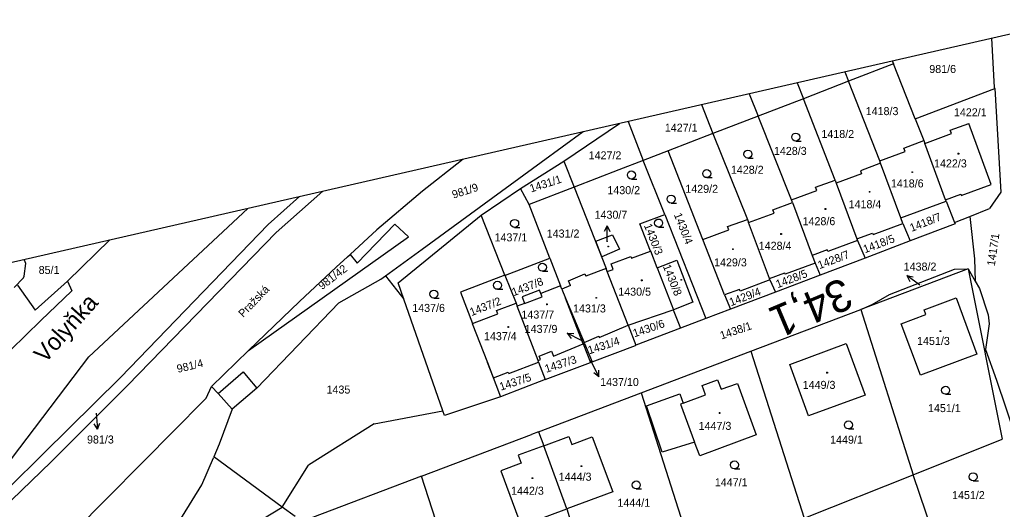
# Model space of a CAD drawing. Extents: x -805730 to -804640, y -1150889 to -1150366.
# Drawn here: x -805108.7 to -804924.5, y -1150504.4 to -1150412.8 of the extents above; entities that cross this region are included whole.
import ezdxf

# ---------------------------------------------------------------- set-up
doc = ezdxf.new("R2010")
doc.units = 0
for name, color, linetype in [('Default', 7, 'Continuous'), ('formát', 7, 'Continuous'), ('kilometráž - vrstava 7', 7, 'Continuous'), ('kn_celek - Cisla parcel pomocna', 7, 'Continuous'), ('kn_celek - Cisla pozemkovych parcel', 7, 'Continuous'), ('kn_celek - Cisla stavebnich parcel', 7, 'Continuous'), ('kn_celek - Dalsi prvky mapy popis', 7, 'Continuous'), ('kn_celek - Hranice parcel', 7, 'Continuous'), ('kn_celek - Vnitrni kresby', 7, 'Continuous'), ('kn_celek - Znacky budov', 7, 'Continuous'), ('kn_celek - Znacky kultur', 7, 'Continuous')]:
    doc.layers.add(name, color=color, linetype=linetype)

# ---------------------------------------------------------------- blocks, each defined once
blk = doc.blocks.new('304')
at = {"layer": 'Default'}
blk.add_line((-0.1, 0), (9.9, 0), dxfattribs=at)
blk.add_circle((-0.1, 7.5), 7.5, dxfattribs=at)
blk = doc.blocks.new('402')
at = {"layer": 'Default'}
for p, q in [((-0.8, 0.8), (0.7, 0.8)), ((-0.8, 0.8), (-0.8, -0.7)), ((0.7, 0.8), (0.7, -0.7)), ((0.7, -0.7), (-0.8, -0.7))]:
    blk.add_line(p, q, dxfattribs=at)
blk = doc.blocks.new('Z61')
at = {"layer": 'Default'}
for p, q in [((0, 0), (30, 0)), ((30, 0), (19.2, 5.3)), ((30, 0), (19.2, -5.3))]:
    blk.add_line(p, q, dxfattribs=at)

msp = doc.modelspace()

# ---------------------------------------------------------------- linework, layer by layer
at = {"layer": 'formát'}
msp.add_line((-804911.33, -1150412.76), (-805116.05, -1150459.54), dxfattribs=at)
at = {"layer": 'kn_celek - Cisla parcel pomocna'}
for p, q in [((-805002.99, -1150473.03), (-805003.39, -1150472.83)), ((-805001.75, -1150476.54), (-805001.53, -1150476.96))]:
    msp.add_line(p, q, dxfattribs=at)
at = {"layer": 'kn_celek - Hranice parcel'}
for p, q in [((-804925.96, -1150425.46), (-804926.47, -1150416.22)), ((-804945.14, -1150420.48), (-804944.93, -1150421.05)), ((-804944.93, -1150421.05), (-804953.35, -1150424.29)), ((-804940.85, -1150431.33), (-804944.93, -1150421.05)), ((-804954.05, -1150422.52), (-804953.35, -1150424.29)), ((-804962.97, -1150424.56), (-804961.8, -1150427.56)), ((-804953.35, -1150424.29), (-804961.8, -1150427.56)), ((-804947.5, -1150439.18), (-804953.35, -1150424.29)), ((-804940.85, -1150431.33), (-804925.94, -1150425.67)), ((-804925.94, -1150425.67), (-804925.96, -1150425.46)), ((-804925.94, -1150425.67), (-804924.82, -1150445.04)), ((-804971.98, -1150426.62), (-804970.29, -1150430.83)), ((-804961.8, -1150427.56), (-804970.29, -1150430.83)), ((-804955.86, -1150442.78), (-804961.8, -1150427.56)), ((-804980.9, -1150428.66), (-804978.77, -1150434.1)), ((-804970.29, -1150430.83), (-804978.77, -1150434.1)), ((-804964.03, -1150446.5), (-804970.29, -1150430.83)), ((-804940.85, -1150431.33), (-804939.24, -1150435.41)), ((-805006.72, -1150439.25), (-804996.26, -1150432.17)), ((-804994.64, -1150431.8), (-804991.84, -1150439.15)), ((-804934.3, -1150433.46), (-804930.82, -1150432.17)), ((-804934.07, -1150434.1), (-804934.3, -1150433.46)), ((-804926.59, -1150443.6), (-804930.82, -1150432.17)), ((-805010.94, -1150439.46), (-805003.06, -1150433.72)), ((-804978.77, -1150434.1), (-804987.17, -1150437.34)), ((-804978.77, -1150434.1), (-804972.3, -1150450.15)), ((-804939.04, -1150435.94), (-804934.07, -1150434.1)), ((-804942.95, -1150436.79), (-804939.24, -1150435.41)), ((-804942.73, -1150437.41), (-804942.95, -1150436.79)), ((-804939.24, -1150435.41), (-804939.04, -1150435.94)), ((-804935.14, -1150446.5), (-804939.04, -1150435.94)), ((-805025.57, -1150438.87), (-805025.92, -1150439.12)), ((-804987.17, -1150437.34), (-804991.84, -1150439.15)), ((-804980.64, -1150453.92), (-804987.17, -1150437.34)), ((-804947.5, -1150439.18), (-804942.73, -1150437.41)), ((-805033.29, -1150455.72), (-805010.94, -1150439.46)), ((-805025.92, -1150439.12), (-805033.21, -1150444.86)), ((-805014.86, -1150444.38), (-805006.72, -1150439.25)), ((-805006.72, -1150439.25), (-805004.8, -1150444.14)), ((-804991.84, -1150439.15), (-804996.39, -1150440.9)), ((-804987.78, -1150449.21), (-804991.84, -1150439.15)), ((-804947.35, -1150439.63), (-804951.12, -1150441.03)), ((-804947.35, -1150439.63), (-804947.5, -1150439.18)), ((-804943.54, -1150449.86), (-804947.35, -1150439.63)), ((-804996.39, -1150440.9), (-805004.8, -1150444.14)), ((-804950.91, -1150441.62), (-804955.64, -1150443.37)), ((-804951.12, -1150441.03), (-804950.91, -1150441.62)), ((-805022.22, -1150449.34), (-805014.86, -1150444.38)), ((-805013.21, -1150447.39), (-805014.86, -1150444.38)), ((-805004.8, -1150444.14), (-805013.21, -1150447.39)), ((-805004.8, -1150444.14), (-804998.8, -1150459.32)), ((-804959.52, -1150444.15), (-804955.86, -1150442.78)), ((-804959.3, -1150444.74), (-804959.52, -1150444.15)), ((-804955.86, -1150442.78), (-804955.64, -1150443.37)), ((-804955.64, -1150443.37), (-804951.76, -1150453.81)), ((-804932.21, -1150445.68), (-804926.59, -1150443.6)), ((-805062.11, -1150451.14), (-805056.24, -1150445.88)), ((-805060.64, -1150452.61), (-805051.86, -1150444.87)), ((-805033.21, -1150444.86), (-805041.78, -1150452.12)), ((-804964.03, -1150446.5), (-804959.3, -1150444.74)), ((-804935.14, -1150446.5), (-804932.3, -1150445.45)), ((-804932.3, -1150445.45), (-804932.21, -1150445.68)), ((-804924.82, -1150445.04), (-804926.9, -1150448.13)), ((-805065.94, -1150448.09), (-805095.74, -1150475.92)), ((-805009.33, -1150457.41), (-805013.21, -1150447.39)), ((-804967.51, -1150448.35), (-804963.85, -1150446.99)), ((-804963.85, -1150446.99), (-804964.03, -1150446.5)), ((-804963.85, -1150446.99), (-804960.15, -1150456.93)), ((-804943.54, -1150449.86), (-804935.05, -1150446.74)), ((-804935.05, -1150446.74), (-804935.14, -1150446.5)), ((-804935.05, -1150446.74), (-804933.47, -1150450.72)), ((-804930.64, -1150449.61), (-804926.9, -1150448.13)), ((-805037.75, -1150462.05), (-805022.22, -1150449.34)), ((-805017.74, -1150460.61), (-805022.22, -1150449.34)), ((-804992.45, -1150450.99), (-804987.78, -1150449.21)), ((-804987.78, -1150449.21), (-804980.08, -1150468.73)), ((-804972.08, -1150450.74), (-804967.29, -1150448.96)), ((-804967.29, -1150448.96), (-804967.51, -1150448.35)), ((-804943.15, -1150450.92), (-804943.54, -1150449.86)), ((-804933.47, -1150450.72), (-804930.64, -1150449.61)), ((-804930.64, -1150449.61), (-804929.74, -1150457.55)), ((-805089.82, -1150479.75), (-805062.11, -1150451.14)), ((-805045.42, -1150458.33), (-805038.38, -1150451.03)), ((-805038.38, -1150451.03), (-805035.81, -1150453.4)), ((-804990.46, -1150456.1), (-804992.45, -1150450.99)), ((-804976.01, -1150451.51), (-804972.3, -1150450.15)), ((-804975.79, -1150452.11), (-804976.01, -1150451.51)), ((-804972.3, -1150450.15), (-804972.08, -1150450.74)), ((-804968.18, -1150461.2), (-804972.08, -1150450.74)), ((-804948.75, -1150453.01), (-804943.15, -1150450.92)), ((-804943.15, -1150450.92), (-804941.8, -1150454.19)), ((-804933.37, -1150450.99), (-804941.8, -1150454.19)), ((-804933.47, -1150450.72), (-804933.37, -1150450.99)), ((-805088.49, -1150481.25), (-805060.64, -1150452.61)), ((-805065.83, -1150474.73), (-805035.81, -1150453.4)), ((-805046.78, -1150456.73), (-805041.78, -1150452.12)), ((-805000.72, -1150454.24), (-804997.56, -1150453.02)), ((-804997.56, -1150453.02), (-804996.29, -1150455.7)), ((-804980.64, -1150453.92), (-804975.79, -1150452.11)), ((-804951.76, -1150453.81), (-804948.86, -1150452.73)), ((-804948.86, -1150452.73), (-804948.75, -1150453.01)), ((-805091.78, -1150454), (-805099.75, -1150461.7)), ((-804999.59, -1150457.14), (-805000.72, -1150454.24)), ((-804976.62, -1150464.31), (-804980.64, -1150453.92)), ((-804951.66, -1150454.09), (-804957.23, -1150456.16)), ((-804951.76, -1150453.81), (-804951.66, -1150454.09)), ((-804951.66, -1150454.09), (-804950.22, -1150457.39)), ((-804941.8, -1150454.19), (-804950.22, -1150457.39)), ((-805049.37, -1150459.12), (-805047.26, -1150457.17)), ((-805047.26, -1150457.17), (-805046.78, -1150456.73)), ((-805046.78, -1150456.73), (-805045.42, -1150458.33)), ((-805040.15, -1150460.71), (-805033.29, -1150455.72)), ((-805017.67, -1150460.58), (-805009.33, -1150457.41)), ((-805009.33, -1150457.41), (-805007.32, -1150462.6)), ((-804996.29, -1150455.7), (-804999.59, -1150457.14)), ((-804997.85, -1150458.47), (-804994.15, -1150457.13)), ((-804994.15, -1150457.13), (-804994.05, -1150457.41)), ((-804994.05, -1150457.41), (-804990.46, -1150456.1)), ((-804990.46, -1150456.1), (-804990.43, -1150456.09)), ((-804989.2, -1150459.22), (-804990.43, -1150456.09)), ((-804957.33, -1150455.88), (-804960.15, -1150456.93)), ((-804960.15, -1150456.93), (-804959.58, -1150458.33)), ((-804950.22, -1150457.39), (-804958.64, -1150460.58)), ((-804957.23, -1150456.16), (-804957.33, -1150455.88)), ((-805107.65, -1150458.1), (-805107.89, -1150457.68)), ((-805107.85, -1150460.8), (-805107.58, -1150458.42)), ((-805107.58, -1150458.42), (-805107.65, -1150458.1)), ((-805056.28, -1150465.5), (-805049.37, -1150459.12)), ((-804997.47, -1150459.51), (-804997.85, -1150458.47)), ((-804989.2, -1150459.22), (-804985.56, -1150457.81)), ((-804989.2, -1150459.22), (-804986.16, -1150467.06)), ((-804985.56, -1150457.81), (-804982.53, -1150465.66)), ((-804959.58, -1150458.33), (-804965.21, -1150460.41)), ((-804959.58, -1150458.33), (-804958.64, -1150460.58)), ((-804929.74, -1150457.55), (-804929.58, -1150461.7)), ((-805108.02, -1150461.11), (-805107.85, -1150460.8)), ((-805040.99, -1150461.32), (-805040.15, -1150460.71)), ((-805040.15, -1150460.71), (-805036.69, -1150465.09)), ((-805017.74, -1150460.61), (-805026.06, -1150463.77)), ((-805017.67, -1150460.58), (-805017.74, -1150460.61)), ((-805017.74, -1150460.61), (-805015.66, -1150465.83)), ((-805005.86, -1150461.65), (-805002.76, -1150460.36)), ((-805002.76, -1150460.36), (-805002.59, -1150460.77)), ((-804998.8, -1150459.32), (-805002.59, -1150460.77)), ((-804998.57, -1150459.91), (-804998.8, -1150459.32)), ((-804998.57, -1150459.91), (-804997.47, -1150459.51)), ((-804994.64, -1150469.99), (-804998.57, -1150459.91)), ((-804968.18, -1150461.2), (-804965.31, -1150460.13)), ((-804958.64, -1150460.58), (-804967.06, -1150463.78)), ((-804965.21, -1150460.41), (-804965.31, -1150460.13)), ((-804930.92, -1150459.44), (-804951.04, -1150467.05)), ((-804945.64, -1150464.19), (-804933.47, -1150459.45)), ((-804933.47, -1150459.45), (-804930.92, -1150459.44)), ((-804930.92, -1150459.44), (-804924.52, -1150491.32)), ((-804930.92, -1150459.44), (-804929.58, -1150461.7)), ((-805109.72, -1150462.89), (-805108.02, -1150461.11)), ((-805109.13, -1150462.48), (-805105.81, -1150467.16)), ((-805105.81, -1150467.16), (-805099.75, -1150461.7)), ((-805099.75, -1150461.7), (-805098.94, -1150463.51)), ((-805048.88, -1150465.79), (-805040.99, -1150461.32)), ((-805036.69, -1150465.09), (-805037.75, -1150462.05)), ((-805007.32, -1150462.6), (-805011.02, -1150464.02)), ((-805007.08, -1150463.23), (-805007.32, -1150462.6)), ((-805005.48, -1150462.56), (-805007.08, -1150463.23)), ((-805005.48, -1150462.56), (-805005.86, -1150461.65)), ((-804968.08, -1150461.49), (-804973.66, -1150463.57)), ((-804968.08, -1150461.49), (-804968.18, -1150461.2)), ((-804968.08, -1150461.49), (-804967.06, -1150463.78)), ((-804929.58, -1150461.7), (-804928.77, -1150463.07)), ((-805098.94, -1150463.51), (-805104.72, -1150469.11)), ((-805026.06, -1150463.77), (-805023.82, -1150469.64)), ((-805011.25, -1150463.41), (-805014.55, -1150464.68)), ((-805014.55, -1150464.68), (-805014.08, -1150465.89)), ((-805011.02, -1150464.02), (-805011.25, -1150463.41)), ((-805007.08, -1150463.23), (-805006.39, -1150464.89)), ((-804973.77, -1150463.28), (-804976.62, -1150464.31)), ((-804976.62, -1150464.31), (-804975.47, -1150466.98)), ((-804967.06, -1150463.78), (-804975.47, -1150466.98)), ((-804973.66, -1150463.57), (-804973.77, -1150463.28)), ((-804948.92, -1150466.09), (-804945.64, -1150464.19)), ((-804928.77, -1150463.07), (-804927.15, -1150468.03)), ((-805065.83, -1150474.73), (-805056.28, -1150465.5)), ((-805064.25, -1150481.77), (-805048.88, -1150465.79)), ((-805029.41, -1150485.99), (-805036.69, -1150465.09)), ((-805019.31, -1150467.21), (-805015.66, -1150465.83)), ((-805015.66, -1150465.83), (-805015.45, -1150466.42)), ((-805014.08, -1150465.89), (-805015.45, -1150466.42)), ((-805011.54, -1150476.59), (-805015.45, -1150466.42)), ((-805006.39, -1150464.89), (-805002.93, -1150473.2)), ((-805003.08, -1150473.48), (-805006.39, -1150464.89)), ((-804982.53, -1150465.66), (-804986.16, -1150467.06)), ((-804951.04, -1150467.05), (-804948.92, -1150466.09)), ((-804939.15, -1150467.07), (-804933.18, -1150464.83)), ((-804933.18, -1150464.83), (-804929.31, -1150475.36)), ((-805023.82, -1150469.64), (-805019.07, -1150467.82)), ((-805019.07, -1150467.82), (-805019.31, -1150467.21)), ((-804994.64, -1150469.99), (-804986.2, -1150467.07)), ((-804986.16, -1150467.06), (-804986.2, -1150467.07)), ((-804986.2, -1150467.07), (-804984.86, -1150470.54)), ((-804975.47, -1150466.98), (-804980.08, -1150468.73)), ((-804971.65, -1150474.85), (-804951.04, -1150467.05)), ((-804951.04, -1150467.05), (-804941.26, -1150497.99)), ((-804943.5, -1150469.71), (-804938.88, -1150467.94)), ((-804938.88, -1150467.94), (-804939.15, -1150467.07)), ((-804927.15, -1150468.03), (-804927.01, -1150469.74)), ((-805104.72, -1150469.11), (-805110.36, -1150474.57)), ((-805023.82, -1150469.64), (-805023.89, -1150469.67)), ((-805023.89, -1150469.67), (-805021.05, -1150476.92)), ((-805000.08, -1150472.25), (-804994.64, -1150469.99)), ((-804994.64, -1150469.99), (-804993.19, -1150473.71)), ((-804980.08, -1150468.73), (-804984.86, -1150470.54)), ((-804939.83, -1150479.34), (-804943.5, -1150469.71)), ((-804927.01, -1150469.74), (-804927.7, -1150474.5)), ((-805002.93, -1150473.2), (-805000.16, -1150472.05)), ((-805000.16, -1150472.05), (-805000.08, -1150472.25)), ((-804984.86, -1150470.54), (-804993.19, -1150473.71)), ((-805008.65, -1150475.74), (-805003.08, -1150473.48)), ((-805003.08, -1150473.48), (-805002.85, -1150473.39)), ((-805003.08, -1150473.48), (-805001.74, -1150476.95)), ((-805002.85, -1150473.39), (-805002.93, -1150473.2)), ((-805002.85, -1150473.39), (-805001.43, -1150476.83)), ((-805001.43, -1150476.83), (-804993.3, -1150473.75)), ((-804993.19, -1150473.71), (-804993.3, -1150473.75)), ((-804964.38, -1150477.32), (-804953.81, -1150473.42)), ((-804953.81, -1150473.42), (-804950.26, -1150483.04)), ((-805072.76, -1150481.42), (-805065.83, -1150474.73)), ((-805011.36, -1150475.74), (-805009.03, -1150474.8)), ((-805011.09, -1150476.41), (-805011.36, -1150475.74)), ((-805009.03, -1150474.8), (-805008.65, -1150475.74)), ((-804992.2, -1150482.63), (-804971.65, -1150474.85)), ((-804971.65, -1150474.85), (-804961.69, -1150506.13)), ((-804929.31, -1150475.36), (-804939.83, -1150479.34)), ((-804927.7, -1150474.5), (-804925.63, -1150480.28)), ((-805111.59, -1150496.78), (-805095.74, -1150475.92)), ((-805021.05, -1150476.92), (-805018.6, -1150483.36)), ((-805019.92, -1150479.82), (-805021.05, -1150476.92)), ((-805017.02, -1150479.03), (-805011.43, -1150476.87)), ((-805011.54, -1150476.59), (-805011.09, -1150476.41)), ((-805011.43, -1150476.87), (-805011.54, -1150476.59)), ((-805011.43, -1150476.87), (-805010.19, -1150480.16)), ((-805010.19, -1150480.16), (-805001.74, -1150476.95)), ((-805001.74, -1150476.95), (-805001.43, -1150476.83)), ((-804960.83, -1150486.94), (-804964.38, -1150477.32)), ((-805071.49, -1150482.75), (-805066.84, -1150478.72)), ((-805066.84, -1150478.72), (-805065.96, -1150479.76)), ((-805019.92, -1150479.82), (-805017.13, -1150478.76)), ((-805017.13, -1150478.76), (-805017.02, -1150479.03)), ((-805104.33, -1150494.08), (-805089.82, -1150479.75)), ((-805102.8, -1150495.57), (-805088.49, -1150481.25)), ((-805065.96, -1150479.76), (-805064.25, -1150481.77)), ((-805010.19, -1150480.16), (-805018.6, -1150483.36)), ((-804980.8, -1150481.26), (-804977.89, -1150480.19)), ((-804980.16, -1150483.02), (-804980.8, -1150481.26)), ((-804977.89, -1150480.19), (-804977.24, -1150481.95)), ((-804977.24, -1150481.95), (-804974.15, -1150480.88)), ((-804974.15, -1150480.88), (-804970.66, -1150490.48)), ((-804925.63, -1150480.28), (-804920.17, -1150496.45)), ((-805073.74, -1150483.62), (-805072.76, -1150481.42)), ((-805072.76, -1150481.42), (-805071.49, -1150482.75)), ((-805064.25, -1150481.77), (-805068.87, -1150485.69)), ((-805011.47, -1150489.91), (-804992.2, -1150482.63)), ((-804992.2, -1150482.63), (-804982.1, -1150514.26)), ((-804991.24, -1150485.06), (-804984.99, -1150482.82)), ((-804984.99, -1150482.82), (-804984.32, -1150484.55)), ((-804984.32, -1150484.55), (-804980.16, -1150483.02)), ((-804950.26, -1150483.04), (-804960.83, -1150486.94)), ((-805079.46, -1150489.37), (-805074.53, -1150484.41)), ((-805074.53, -1150484.41), (-805073.74, -1150483.62)), ((-805018.6, -1150483.36), (-805029.11, -1150486.86)), ((-805068.87, -1150485.69), (-805071.3, -1150492.22)), ((-805042.24, -1150488.46), (-805029.41, -1150485.99)), ((-805029.11, -1150486.86), (-805029.41, -1150485.99)), ((-804988.29, -1150493.74), (-804991.24, -1150485.06)), ((-805042.24, -1150488.46), (-805054.55, -1150496.18)), ((-805079.5, -1150489.41), (-805112.27, -1150522.42)), ((-805079.46, -1150489.37), (-805079.5, -1150489.41)), ((-805033.4, -1150498.22), (-805012.78, -1150490.41)), ((-805011.47, -1150489.91), (-805012.78, -1150490.41)), ((-805011.47, -1150489.91), (-805010.49, -1150492.55)), ((-804970.66, -1150490.48), (-804981.23, -1150494.42)), ((-805071.3, -1150492.22), (-805072.32, -1150494.62)), ((-805010.49, -1150492.55), (-805005.78, -1150490.79)), ((-805005.78, -1150490.79), (-805005.2, -1150492.28)), ((-805005.2, -1150492.28), (-805001.38, -1150490.85)), ((-805001.38, -1150490.85), (-804997.51, -1150501.2)), ((-804982.19, -1150491.84), (-804988.29, -1150493.74)), ((-804981.23, -1150494.42), (-804982.19, -1150491.84)), ((-804941.26, -1150497.99), (-804924.52, -1150491.32)), ((-805110.75, -1150500.43), (-805104.33, -1150494.08)), ((-805010.49, -1150492.55), (-805015.26, -1150494.31)), ((-805006.12, -1150504.36), (-805010.49, -1150492.55)), ((-805110.22, -1150502.75), (-805102.8, -1150495.57)), ((-805074.55, -1150499.86), (-805072.39, -1150494.78)), ((-805072.32, -1150494.62), (-805072.39, -1150494.78)), ((-805059.52, -1150504.03), (-805072.32, -1150494.62)), ((-805014.71, -1150495.8), (-805018.53, -1150497.21)), ((-805015.26, -1150494.31), (-805014.71, -1150495.8)), ((-805059.52, -1150504.03), (-805054.55, -1150496.18)), ((-805018.53, -1150497.21), (-805014.72, -1150507.54)), ((-805033.4, -1150498.22), (-805053.85, -1150505.95)), ((-805022.97, -1150530.54), (-805033.4, -1150498.22)), ((-804961.69, -1150506.13), (-804941.26, -1150497.99)), ((-804935.25, -1150515.44), (-804941.26, -1150497.99)), ((-805082.65, -1150512.94), (-805074.55, -1150499.86)), ((-804997.51, -1150501.2), (-805006.12, -1150504.36)), ((-805069.04, -1150509.76), (-805059.52, -1150504.03)), ((-805057.1, -1150505.8), (-805059.52, -1150504.03)), ((-805014.72, -1150507.54), (-805006.12, -1150504.36)), ((-805006.12, -1150504.36), (-805000.8, -1150521.71))]:
    msp.add_line(p, q, dxfattribs=at)
at = {"layer": 'kn_celek - Vnitrni kresby'}
for p, q in [((-805014.08, -1150465.89), (-805010.78, -1150464.63)), ((-805010.78, -1150464.63), (-805011.02, -1150464.02)), ((-805071.49, -1150482.75), (-805068.87, -1150485.69)), ((-804984.32, -1150484.55), (-804984.84, -1150484.74)), ((-804984.84, -1150484.74), (-804982.19, -1150491.84))]:
    msp.add_line(p, q, dxfattribs=at)

# ---------------------------------------------------------------- block references
at = {"layer": 'kn_celek - Cisla parcel pomocna'}
for p, xscale, yscale, rotation in [((-804998.6, -1150454.34), 0.1, 0.10000000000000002, 90.00000000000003), ((-804940.01, -1150462.49), 0.09999999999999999, 0.1, 143.12997000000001), ((-805003.39, -1150472.83), 0.1, 0.09999999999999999, 153.35739), ((-805001.53, -1150476.96), 0.10000000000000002, 0.1, -62.40266999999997), ((-805094.37, -1150486.45), 0.10000000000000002, 0.1, -85.46571000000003)]:
    msp.add_blockref('Z61', p, dxfattribs=dict(at, xscale=xscale, yscale=yscale, rotation=rotation))
at = {"layer": 'kn_celek - Znacky budov', "xscale": 0.1, "yscale": 0.10000000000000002}
for p in [(-804932.75, -1150437.84), (-804941.41, -1150441.32), (-804949.42, -1150444.99), (-804957.7, -1150448.2), (-804965.99, -1150452.9), (-804998.39, -1150455.23), (-804975.03, -1150455.73), (-804992.12, -1150461.58), (-804984.71, -1150461.47), (-805000.65, -1150464.84), (-805009.91, -1150466.06), (-805017.15, -1150470.31), (-804936.14, -1150471.09), (-805003.3, -1150472.6), (-804957.38, -1150478.86), (-804977.53, -1150486.42), (-805003.43, -1150496.37), (-805012.61, -1150498.61)]:
    msp.add_blockref('402', p, dxfattribs=at)
at = {"layer": 'kn_celek - Znacky kultur', "xscale": 0.1, "yscale": 0.10000000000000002}
for p in [(-804963.23, -1150435.48), (-804972.21, -1150438.68), (-804979.92, -1150442.34), (-804994.03, -1150442.59), (-804986.59, -1150447.09), (-805015.92, -1150451.67), (-804988.94, -1150451.58), (-805010.72, -1150459.87), (-805019.13, -1150463.25), (-805031.07, -1150464.88), (-804935.14, -1150482.9), (-804953.35, -1150489.39), (-804974.72, -1150496.87), (-804929.98, -1150499.11), (-804993.13, -1150500.63)]:
    msp.add_blockref('304', p, dxfattribs=at)

# ---------------------------------------------------------------- texts
at = {"layer": 'kilometráž - vrstava 7'}
msp.add_text('34,1', height=6, rotation=202.8502, dxfattribs=at).set_placement((-804954.34, -1150460.92))
at = {"layer": 'kn_celek - Cisla parcel pomocna'}
for s, p in [('1430/7', (-805000.95, -1150450.03)), ('1438/2', (-804943.01, -1150459.74)), ('1437/9', (-805014.05, -1150471.41)), ('1437/10', (-804999.9, -1150481.35)), ('981/3', (-805096.09, -1150492.12))]:
    msp.add_text(s, height=1.5, dxfattribs=at).set_placement(p)
at = {"layer": 'kn_celek - Cisla pozemkovych parcel'}
for s, height, p in [('981/6', 1.5, (-804938.21, -1150422.74)), ('1418/3', 1.5, (-804950.13, -1150430.63)), ('1422/1', 1.5, (-804933.59, -1150430.85)), ('1427/1', 1.5, (-804987.78, -1150433.73)), ('1418/2', 1.5, (-804958.43, -1150434.91)), ('1428/3', 1.5, (-804967.33, -1150438.08)), ('1427/2', 1.5, (-805002.06, -1150438.91)), ('1428/2', 1.5, (-804975.4, -1150441.61)), ('1430/2', 1.5, (-804998.55, -1150445.43)), ('1429/2', 1.5, (-804983.94, -1150445.18)), ('1437/1', 1.5, (-805019.7, -1150454.27)), ('1431/2', 1.5, (-805009.92, -1150453.55)), ('85/1', 1.5, (-805105.15, -1150460.37)), ('1438/2', 0.1, (-804940.01, -1150462.46)), ('1437/6', 1.5, (-805035.13, -1150467.48)), ('1437/10', 0.1, (-805002.05, -1150476.51)), ('1435', 1.5, (-805051.19, -1150482.77)), ('1451/1', 1.5, (-804938.45, -1150486.24)), ('1449/1', 1.5, (-804956.8, -1150492.15)), ('1447/1', 1.5, (-804978.41, -1150500.13)), ('1451/2', 1.5, (-804933.94, -1150502.53)), ('1444/1', 1.5, (-804996.66, -1150503.97))]:
    msp.add_text(s, height=height, dxfattribs=at).set_placement(p)
for s, rotation, p in [('1431/1', 18, (-805012.84, -1150445.13)), ('981/9', 17.6379, (-805027.4, -1150446.28)), ('1430/4', 291.6, (-804986.11, -1150449.27)), ('1418/7', 21.6, (-804941.52, -1150452.51)), ('1430/3', 291.6, (-804991.73, -1150451.28)), ('1418/5', 20.7, (-804950.27, -1150456.51)), ('1417/1', 81.8339, (-804925.93, -1150458.95)), ('1428/7', 20.7, (-804958.78, -1150459.48)), ('981/42', 37.4128, (-805052.03, -1150463.42)), ('1437/8', 21.0607, (-805016.13, -1150464.55)), ('1428/5', 20.7, (-804966.64, -1150463.05)), ('1429/4', 20.7, (-804975.37, -1150466.42)), ('1437/2', 21.5339, (-805024.01, -1150468.28)), ('1430/6', 18.9, (-804993.47, -1150472.25)), ('1438/1', 18.8433, (-804977.15, -1150472.66)), ('1431/4', 18, (-805001.93, -1150475.42)), ('1437/3', 18, (-805010.01, -1150478.89)), ('981/4', 13.5, (-805079.06, -1150478.9)), ('1437/5', 18, (-805018.51, -1150482.23))]:
    msp.add_text(s, height=1.5, rotation=rotation, dxfattribs=at).set_placement(p)
at = {"layer": 'kn_celek - Cisla stavebnich parcel'}
for s, height, p in [('1422/3', 1.5, (-804937.32, -1150440.42)), ('1418/6', 1.5, (-804945.41, -1150444.17)), ('1418/4', 1.5, (-804953.33, -1150448.06)), ('1428/6', 1.5, (-804961.96, -1150451.24)), ('1430/7', 0.1, (-804998.6, -1150454.31)), ('1428/4', 1.5, (-804970.18, -1150455.84)), ('1429/3', 1.5, (-804978.55, -1150458.95)), ('1430/5', 1.5, (-804996.51, -1150464.44)), ('1431/3', 1.5, (-805004.98, -1150467.58)), ('1437/7', 1.5, (-805014.66, -1150468.73)), ('1437/4', 1.5, (-805021.68, -1150472.77)), ('1451/3', 1.5, (-804940.5, -1150473.66)), ('1449/3', 1.5, (-804961.94, -1150481.89)), ('1447/3', 1.5, (-804981.45, -1150489.57)), ('1444/3', 1.5, (-805007.66, -1150499.09)), ('1442/3', 1.5, (-805016.6, -1150501.71))]:
    msp.add_text(s, height=height, dxfattribs=at).set_placement(p)
for s, height, rotation, p in [('1430/8', 1.5, 291.6, (-804988.17, -1150458.93)), ('1437/9', 0.1, 297.3924, (-805003.22, -1150472.95))]:
    msp.add_text(s, height=height, rotation=rotation, dxfattribs=at).set_placement(p)
at = {"layer": 'kn_celek - Dalsi prvky mapy popis'}
for s, height, rotation, p in [('Pražská', 1.5, 46.2517, (-805066.8, -1150468.61)), ('Volyňka', 3.2, 48.1495, (-805103.96, -1150477.23))]:
    msp.add_text(s, height=height, rotation=rotation, dxfattribs=at).set_placement(p)

doc.saveas('drawing.dxf')
